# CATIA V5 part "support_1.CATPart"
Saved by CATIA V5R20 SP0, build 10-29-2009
Part number: support_1
Publications: "support1_barre", "support1_pivotcent", "support1_pivotext", "support1_pivotint"
Bounding box of the stored display mesh (mm): x 90 to 110, y -350 to 50, z 0 to 0
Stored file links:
  C:\Users\Noëllie\Documents\IFMA\2A\S3\IAO\Projet Artobolevski\Catia\support_1.CATPart
  C:\Users\Noëllie\Documents\IFMA\2A\S3\IAO\Projet Artobolevski\Catia\Artobolevski 782.CATProduct
  C:\Users\Noëllie\Documents\IFMA\2A\S3\IAO\Projet Artobolevski\Catia\plateau_2.CATPart
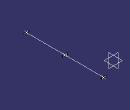
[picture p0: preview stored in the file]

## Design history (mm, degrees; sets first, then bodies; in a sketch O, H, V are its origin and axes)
Set1
  Point1 "B1g": linked copy from another document
  Point2 "B1d": linked copy from another document
  Point3 "A1": linked copy from another document
Body1 (main body)
  Line1 "support1_barre": type PtPt, FirstPoint Point1, SecondPoint Point2
  Line2 "support1_pivotcent": type PtDir, RefPoint Point3, Direction yz-plane, Start 10, End -10
  Line3 "support1_pivotext": type PtDir, RefPoint Point1, Direction yz-plane, Start 10, End -10
  Line4 "support1_pivotint": type PtDir, RefPoint Point2, Direction yz-plane, Start 10, End -10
